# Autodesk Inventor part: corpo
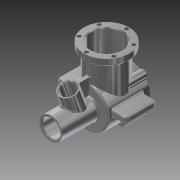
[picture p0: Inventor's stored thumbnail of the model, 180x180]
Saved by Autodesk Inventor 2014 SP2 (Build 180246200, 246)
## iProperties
Created: 2016-04
Part Number: corpo
Material: Genérico
Document SubType Name: Modeling
Designer: Celiberto
Density: 1 g/cm^3
Appearance: Prata
Author: Celiberto
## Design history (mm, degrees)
sketch "Esboço1"
  geometry: C1 r 12 at (0, 0); 1 further point
  constraints: 1 centre point, 1 coincident
  dimensions: "d0" = 24 diameter of C1
extrude "Extrusão1" new body sketch "Esboço1" distance "d1" = 24; taper "d2" = 0 deg
sketch "Esboço2"
  geometry: C1 r 12 at (0, 0) reference; C2 r 6.5 at (0, 0)
  constraints: 1 centre point, 1 coincident
  dimensions: "d3" = 13 diameter of C2
extrude "Extrusão2" join sketch "Esboço2" distance "d4" = 45; taper "d5" = 0 deg
node "Plano de trabalho1"
sketch "Esboço3"
  geometry: L1 (0, 0)-(0, -24.164); L2 (-12, 0)-(12, 0) reference; L3 (-12, -24)-(12, -24) reference; C1 r 13 at (0, -13)
  constraints: 2 end point, 1 centre point, 1 point on line, 1 tangent, 1 vertical
  dimensions: "d7" = 26 diameter of C1
extrude "Extrusão3" join sketch "Esboço3" distance "d8" = 4; taper "d9" = 0 deg
sketch "Esboço4"
  geometry: C1 r 10.5 at (0, 0); 2 further points
  constraints: 1 centre point, 1 coincident, 1 vertical alignment
  dimensions: "d10" = 21 diameter of C1
extrude "Extrusão4" join sketch "Esboço4" stored distance "d11" = 4; taper "d12" = 0 deg
node "Plano de trabalho2"
sketch "Esboço5"
  geometry: L1 (-17.909, -35.3)-(20.37, -35.3); L2 (-12, 0)-(12, 0) reference; 1 further point
  constraints: 2 end point, 1 horizontal
  dimensions: "d14" = 35.3 distance between parallel lines of L1 L2
node "Plano de trabalho3"
sketch "Esboço6"
  geometry: L1 (0.465, -0.008)-(50.921, -0.008); L2 (17.909, 9.325)-(17.909, -8.903); C1 r 5 at (17.909, 0.211); 1 further point
  constraints: 4 end point, 1 centre point, 1 horizontal, 1 midpoint, 1 perpendicular
  dimensions: "d16" = 10 diameter of C1
extrude "Extrusão5" join sketch "Esboço6" stored distance "d17" = 4; taper "d18" = 0 deg
sketch "Esboço7"
  geometry: L1 (-20, -22)-(20, -22); L2 (20, -22)-(20, -4); L3 (20, -4)-(-20, -4); L4 (-20, -4)-(-20, -22); L5 (-20, -22)-(20, -4); L6 (20, -22)-(-20, -4); 4 further points
  constraints: 12 end point, 3 midpoint, 2 parallel, 1 coincident, 1 horizontal, 1 perpendicular, 1 vertical alignment
  dimensions: "d19" = 18 distance of L3.end L1.start; "d20" = 40 distance of L2.end L3.end
extrude "Extrusão6" join sketch "Esboço7" distance "d21" = 3.5; taper "d22" = 0 deg
sketch "Esboço8"
  geometry: L1 (-21.864, 15.482)-(-31.769, 15.482); L2 (-31.769, 15.482)-(-31.769, 3.66); L3 (-31.769, 3.66)-(-20.818, 3.66); L4 (-20.818, 3.66)-(-20.818, 15.482); L5 (-20.818, 15.482)-(-21.864, 15.482); L6 (-62.952, 4.635)-(10.586, 31.401) reference; L7 (-30.403, 16.482)-(-26.77, 6.5) reference; 1 further point
  constraints: 10 end point, 2 parallel, 1 collinear, 1 horizontal, 1 perpendicular
  dimensions: "d23" = 1 distance from line of L1 L7.start
extrude "Extrusão7" join sketch "Esboço8" stored distance "d24" = 2; taper "d25" = 0 deg
sketch "Esboço9"
  geometry: C1 r 12 at (0, 0) reference; C2 r 5 at (0, 0)
  constraints: 1 centre point, 1 coincident
  dimensions: "d26" = 10 diameter of C2
extrude "Extrusão8" cut sketch "Esboço9" stored distance "d27" = 2; taper "d28" = 0 deg
sketch "Esboço10"
  geometry: C1 r 5 at (0, 0) reference; C2 r 12 at (0, 0) reference; C3 r 10.5 at (0, 0)
  constraints: 1 centre point, 1 coincident
  dimensions: "d29" = 21 diameter of C3
extrude "Extrusão9" cut sketch "Esboço10" distance "d30" = 20; taper "d31" = 0 deg
sketch "Esboço11"
  geometry: C1 r 9 at (0, 0); 2 further points
  constraints: 1 centre point, 1 coincident, 1 vertical alignment
  dimensions: "d32" = 18 diameter of C1
extrude "Extrusão10" cut sketch "Esboço11" distance "d33" = 15.3; taper "d34" = 0 deg
sketch "Esboço12"
  geometry: C1 r 9 at (0, 0) reference; C2 r 7 at (0, 0); 1 further point
  constraints: 1 centre point, 1 coincident
  dimensions: "d35" = 14 diameter of C2
extrude "Extrusão11" cut sketch "Esboço12" stored distance "d36" = 15.3; taper "d37" = 0 deg
sketch "Esboço13"
  geometry: C1 r 5 at (0, 0) reference; C2 r 4 at (0, 0); 1 further point
  constraints: 1 centre point, 1 coincident
  dimensions: "d38" = 8 diameter of C2
extrude "Extrusão12" cut sketch "Esboço13" stored distance "d39" = 15.3; taper "d40" = 0 deg
sketch "Esboço14" dims "d41" = 23
  geometry: 4 further points
  constraints: 2 vertical alignment, 1 coincident, 2 other
hole "Furo1" sketch "Esboço14" at (0, 11.5) diameter "d42" = 2.013; stored, may be unused: countersink angle "d46" = 90 deg, drill point angle "d48" = 118 deg; dims "d43" = 2.5, "d44" = 4, "d45" = 2, "d47" = 4
pattern_circular "Padrão circular1" dims angle "d50" = 360 deg
sketch "Esboço15"
  geometry: L1 (16.324, -9)-(-21.272, -9); L2 (15.016, 9)-(-18.878, 9); L3 (-12, 0)-(-20, 0) reference; A1 r 12.25 centre (0, 0) between (8.31, -9) and (-8.31, -9); A2 r 2 centre (8.31, -9) between (6.439, -8.294) and (7.755, -7.079); A3 r 2 centre (-8.31, -9) between (-7.755, -7.079) and (-6.439, -8.294); A4 r 2 centre (8.31, 9) between (7.755, 7.079) and (6.439, 8.294); A5 r 2 centre (-8.31, 9) between (-6.439, 8.294) and (-7.755, 7.079); 2 further points
  constraints: 12 point on circle, 5 centre point, 4 end point, 4 point on line, 1 coincident, 1 horizontal, 1 horizontal alignment, 1 parallel, 9 other
  dimensions: "d52" = 24.5 diameter of A1; "d53" = 9 distance between parallel lines of L2 L3; "d54" = 18 distance between parallel lines of L1 L2; "d55" = 4 diameter of A2; "d56" = 4 diameter of A3; "d57" = 4 diameter of A4; "d58" = 4 diameter of A5
extrude "Extrusão13" join sketch "Esboço15" distance "d59" = 13; taper "d60" = 0 deg
sketch "Esboço16"
  geometry: A1 r 2 centre (8.31, -9) between (6.594, -10.026) and (9.47, -7.37) reference; A2 r 2 centre (8.31, 9) between (9.47, 7.37) and (6.594, 10.026) reference; A3 r 2 centre (-8.31, 9) between (-6.594, 10.026) and (-9.47, 7.37) reference; A4 r 2 centre (-8.31, -9) between (-9.47, -7.37) and (-6.594, -10.026) reference; 4 further points
  constraints: 4 coincident
hole "Furo2" sketch "Esboço16" at (-8.31, -9), (-8.31, 9), (8.31, 9), (8.31, -9) diameter "d61" = 1.567; stored, may be unused: countersink angle "d65" = 90 deg, drill point angle "d67" = 118 deg; dims "d62" = 6, "d63" = 4, "d64" = 2, "d66" = 8
fillet "Arredondamento1" dims "d68" = 2
fillet "Arredondamento2" dims "d69" = 1
chamfer "Chanfro1" distance "d70" = 0.5; stored, may be unused: second distance "d71" = 2, angle "d72" = 45 deg
node "Sólido1"
other parameters: "d6" = 27.8, "d13" = 14.7, "d15" = 20 deg
